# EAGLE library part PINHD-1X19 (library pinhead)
PIN HEADER
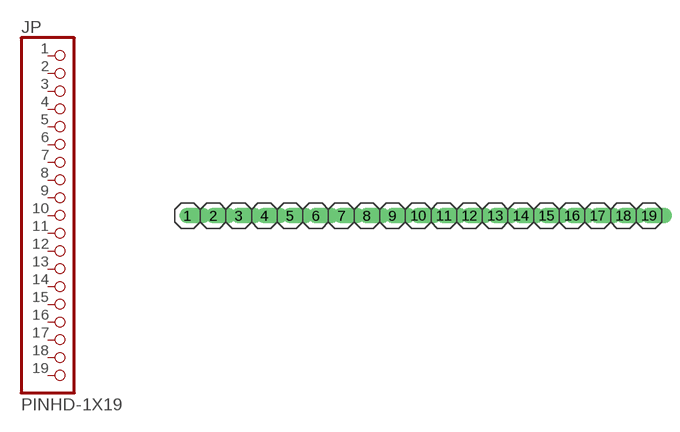
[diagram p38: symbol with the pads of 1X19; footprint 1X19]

Designator prefix JP

## PINHD-1X19  [1X19]
1  1  pas
2  2  pas
3  3  pas
4  4  pas
5  5  pas
6  6  pas
7  7  pas
8  8  pas
9  9  pas
10  10  pas
11  11  pas
12  12  pas
13  13  pas
14  14  pas
15  15  pas
16  16  pas
17  17  pas
18  18  pas
19  19  pas

## Footprint 1X19 (pad centres in mm)
PIN HEADER
drill 1.016 offset: 1 -22.86,0; 2 -20.32,0; 3 -17.78,0; 4 -15.24,0; 5 -12.7,0; 6 -10.16,0; 7 -7.62,0; 8 -5.08,0; 9 -2.54,0; 10 0,0; 11 2.54,0; 12 5.08,0; 13 7.62,0; 14 10.16,0; 15 12.7,0; 16 15.24,0; 17 17.78,0; 18 20.32,0; 19 22.86,0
